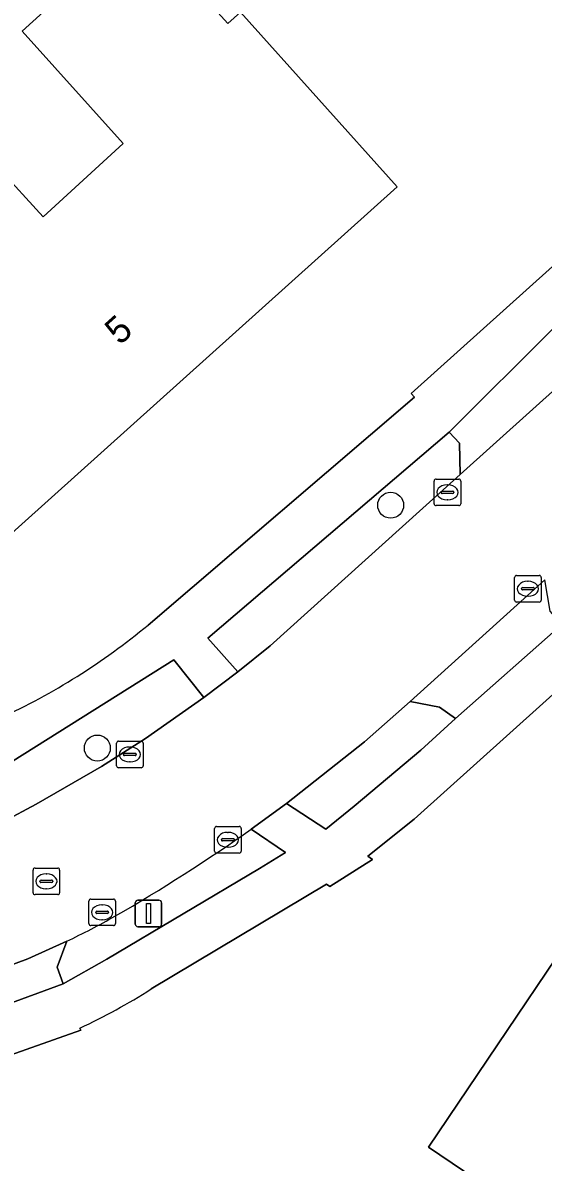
# Model space of a CAD drawing. Extents: x 163266 to 164362, y 381528 to 382286.
# Drawn here: x 163903.13 to 163922.72, y 381642.39 to 381685.27 of the extents above; entities that cross this region are included whole.
import ezdxf

# ---------------------------------------------------------------- set-up
doc = ezdxf.new("R2010")
doc.units = 0
for name, color, linetype in [('IMGEO_Boom', 7, 'Continuous'), ('IMGEO_Erf', 7, 'Continuous'), ('IMGEO_Groenvoorziening', 7, 'Continuous'), ('IMGEO_Haag', 7, 'Continuous'), ('IMGEO_Kolk', 7, 'Continuous'), ('IMGEO_Lichtmast', 7, 'Continuous'), ('IMGEO_Pand', 7, 'Continuous'), ('IMGEO_Pand_nummerreeks', 7, 'Continuous'), ('IMGEO_Rijbaan_lokaal_open', 7, 'Continuous'), ('IMGEO_Rioolput', 7, 'Continuous'), ('IMGEO_Voetpad_open', 7, 'Continuous')]:
    doc.layers.add(name, color=color, linetype=linetype)

msp = doc.modelspace()

# ---------------------------------------------------------------- linework, layer by layer
at = {"layer": 'IMGEO_Boom'}
for centre in [(163916.981, 381667.115), (163905.938, 381657.979)]:
    msp.add_circle(centre, 0.489, dxfattribs=at)
at = {"layer": 'IMGEO_Erf'}
for points in [[(163907.846, 381662.609), (163917.878, 381671.183), (163917.751, 381671.321), (163960.431, 381709.666), (163995.111, 381740.522)], [(163996.245, 381642.873), (163995.343, 381643.451), (163992.948, 381645.106), (163982.444, 381652.18), (163959.631, 381667.581), (163955.118, 381670.638), (163954.017, 381671.266), (163952.935, 381672.069), (163945.749, 381676.984), (163941.834, 381676.838), (163917.871, 381655.298), (163916.12, 381653.912), (163916.297, 381653.78), (163914.696, 381652.772), (163914.563, 381652.851), (163907.959, 381648.913)], [(163905.281, 381647.443), (163905.312, 381647.362), (163892.952, 381643.003), (163890.818, 381639.108), (163894.047, 381628.59)]]:
    msp.add_lwpolyline(points, dxfattribs=at)
for points in [[(163910.845, 381685.239), (163911.326, 381685.672), (163917.227, 381679.103), (163900.114, 381663.732), (163894.791, 381669.649), (163899.822, 381674.244), (163898.16, 381676.126), (163902.193, 381679.825), (163903.898, 381677.967), (163906.916, 381680.724), (163903.102, 381684.959), (163907.494, 381688.938)], [(163933.369, 381643.462), (163931.198, 381644.946), (163926.278, 381637.642), (163918.405, 381642.961), (163926.17, 381654.47), (163934.049, 381649.163), (163933.848, 381648.864), (163936.02, 381647.39)]]:
    msp.add_lwpolyline(points, close=True, dxfattribs=at)
for centre, radius, start, end in [((163891.772, 381681.977), 25.169, 294.6909, 309.6896), ((163895.911, 381667.688), 22.309, 294.837, 302.6892)]:
    msp.add_arc(centre, radius, start, end, dxfattribs=at)
at = {"layer": 'IMGEO_Groenvoorziening'}
for points in [[(163919.566, 381669.451), (163919.183, 381669.863), (163910.092, 381662.118), (163911.229, 381660.85), (163912.446, 381661.828), (163919.599, 381668.268)], [(163909.942, 381659.876), (163908.824, 381661.296), (163901.437, 381656.675), (163899.692, 381655.96), (163894.99, 381654.332), (163892.801, 381653.658), (163893.095, 381652.76), (163894.024, 381652.181), (163897.063, 381653.193), (163901.509, 381654.797), (163902.422, 381655.214), (163903.641, 381655.862), (163906.099, 381657.289), (163907.748, 381658.343)], [(163915.606, 381655.796), (163918.114, 381657.894), (163919.418, 381659.091), (163918.817, 381659.523), (163917.711, 381659.728), (163915.995, 381658.215), (163913.059, 381655.894), (163914.542, 381654.925)]]:
    msp.add_lwpolyline(points, close=True, dxfattribs=at)
msp.add_lwpolyline([(163904.788, 381650.707), (163904.431, 381649.731), (163904.646, 381649.112), (163906.295, 381650.033), (163912.044, 381653.452), (163913.023, 381654.044), (163911.734, 381654.932)], dxfattribs=at)
for centre, radius, start, end in [((163873.791, 381708.646), 65.764, 299.92642, 305.23666), ((163889.367, 381682.518), 35.352, 295.8623, 299.1741)]:
    msp.add_arc(centre, radius, start, end, dxfattribs=at)
at = {"layer": 'IMGEO_Haag'}
for points in [[(163919.599, 381668.268), (163919.566, 381669.451), (163919.183, 381669.863), (163910.092, 381662.118), (163911.229, 381660.85), (163912.446, 381661.828)], [(163894.024, 381652.181), (163897.063, 381653.193), (163901.509, 381654.797), (163902.422, 381655.214), (163903.641, 381655.862), (163906.099, 381657.289), (163907.748, 381658.343), (163909.942, 381659.876), (163908.824, 381661.296), (163901.437, 381656.675), (163899.692, 381655.96), (163894.99, 381654.332), (163892.801, 381653.658), (163893.095, 381652.76)], [(163918.114, 381657.894), (163919.418, 381659.091), (163918.817, 381659.523), (163917.711, 381659.728), (163915.995, 381658.215), (163913.059, 381655.894), (163914.542, 381654.925), (163915.606, 381655.796)]]:
    msp.add_lwpolyline(points, close=True, dxfattribs=at)
msp.add_lwpolyline([(163904.788, 381650.707), (163904.431, 381649.731), (163904.646, 381649.112), (163906.295, 381650.033), (163912.044, 381653.452), (163913.023, 381654.044), (163911.734, 381654.932)], dxfattribs=at)
for centre, radius, start, end in [((163873.791, 381708.646), 65.764, 299.92642, 305.23666), ((163889.367, 381682.518), 35.352, 295.8623, 299.1741)]:
    msp.add_arc(centre, radius, start, end, dxfattribs=at)
at = {"layer": 'IMGEO_Kolk'}
for p, q in [((163918.617, 381667.175), (163918.617, 381668.027)), ((163918.692, 381668.101), (163919.544, 381668.101)), ((163919.618, 381668.027), (163919.618, 381667.175)), ((163918.876, 381667.595), (163918.876, 381667.607)), ((163919.314, 381667.558), (163918.916, 381667.558)), ((163918.919, 381667.644), (163919.317, 381667.644)), ((163919.105, 381667.881), (163919.13, 381667.881)), ((163919.36, 381667.607), (163919.36, 381667.595)), ((163919.544, 381667.101), (163918.692, 381667.101)), ((163919.128, 381667.321), (163919.103, 381667.321)), ((163921.723, 381664.473), (163922.575, 381664.473)), ((163921.648, 381663.547), (163921.648, 381664.399)), ((163922.136, 381664.253), (163922.161, 381664.253)), ((163922.649, 381664.399), (163922.649, 381663.547)), ((163921.907, 381663.967), (163921.907, 381663.979)), ((163922.345, 381663.93), (163921.947, 381663.93)), ((163921.95, 381664.016), (163922.348, 381664.016)), ((163922.159, 381663.693), (163922.134, 381663.693)), ((163922.391, 381663.979), (163922.391, 381663.967)), ((163922.575, 381663.473), (163921.723, 381663.473)), ((163906.663, 381657.312), (163906.663, 381658.164)), ((163906.738, 381658.238), (163907.59, 381658.238)), ((163907.664, 381658.164), (163907.664, 381657.312)), ((163906.922, 381657.732), (163906.922, 381657.744)), ((163907.36, 381657.695), (163906.962, 381657.695)), ((163906.965, 381657.781), (163907.363, 381657.781)), ((163907.151, 381658.018), (163907.176, 381658.018)), ((163907.406, 381657.744), (163907.406, 381657.732)), ((163907.59, 381657.238), (163906.738, 381657.238)), ((163907.174, 381657.458), (163907.149, 381657.458)), ((163910.354, 381654.101), (163910.354, 381654.953)), ((163910.429, 381655.027), (163911.281, 381655.027)), ((163910.842, 381654.807), (163910.867, 381654.807)), ((163911.355, 381654.953), (163911.355, 381654.101)), ((163910.613, 381654.521), (163910.613, 381654.533)), ((163911.051, 381654.484), (163910.653, 381654.484)), ((163910.656, 381654.57), (163911.054, 381654.57)), ((163910.865, 381654.247), (163910.84, 381654.247)), ((163911.097, 381654.533), (163911.097, 381654.521)), ((163911.281, 381654.027), (163910.429, 381654.027))]:
    msp.add_line(p, q, dxfattribs=at)
for points in [[(163918.617, 381667.175), (163918.617, 381668.027)], [(163918.692, 381668.101), (163919.544, 381668.101)], [(163919.618, 381668.027), (163919.618, 381667.175)], [(163919.544, 381667.101), (163918.692, 381667.101)], [(163921.723, 381664.473), (163922.575, 381664.473)], [(163921.648, 381663.547), (163921.648, 381664.399)], [(163922.649, 381664.399), (163922.649, 381663.547)], [(163922.575, 381663.473), (163921.723, 381663.473)], [(163906.663, 381657.312), (163906.663, 381658.164)], [(163906.738, 381658.238), (163907.59, 381658.238)], [(163907.664, 381658.164), (163907.664, 381657.312)], [(163907.59, 381657.238), (163906.738, 381657.238)], [(163910.354, 381654.101), (163910.354, 381654.953)], [(163910.429, 381655.027), (163911.281, 381655.027)], [(163911.355, 381654.953), (163911.355, 381654.101)], [(163911.281, 381654.027), (163910.429, 381654.027)]]:
    msp.add_lwpolyline(points, dxfattribs=at)
for centre, radius, start, end in [((163918.694, 381668.025), 0.0765, 91.552, 178.448), ((163918.694, 381668.025), 0.0765, 91.552, 178.448), ((163919.542, 381668.025), 0.0765, 1.552, 88.448), ((163919.542, 381668.025), 0.0765, 1.552, 88.448), ((163918.916, 381667.604), 0.0403, 85.8775, 175.7526), ((163918.913, 381667.594), 0.0366, 178.938, 274.7102), ((163919.317, 381667.601), 0.043, 264.8664, 352.4533), ((163919.321, 381667.606), 0.0386, 1.7309, 96.639), ((163918.694, 381667.177), 0.0765, 181.552, 268.448), ((163918.694, 381667.177), 0.0765, 181.552, 268.448), ((163919.542, 381667.177), 0.0765, 271.552, 358.448), ((163919.542, 381667.177), 0.0765, 271.552, 358.448), ((163921.725, 381664.397), 0.0765, 91.552, 178.448), ((163921.725, 381664.397), 0.0765, 91.552, 178.448), ((163922.573, 381664.397), 0.0765, 1.552, 88.448), ((163922.573, 381664.397), 0.0765, 1.552, 88.448), ((163921.947, 381663.976), 0.0403, 85.8775, 175.7526), ((163921.944, 381663.966), 0.0366, 178.938, 274.7102), ((163922.348, 381663.973), 0.043, 264.8664, 352.4533), ((163922.352, 381663.978), 0.0386, 1.7309, 96.639), ((163921.725, 381663.549), 0.0765, 181.552, 268.448), ((163921.725, 381663.549), 0.0765, 181.552, 268.448), ((163922.573, 381663.549), 0.0765, 271.552, 358.448), ((163922.573, 381663.549), 0.0765, 271.552, 358.448), ((163906.74, 381658.162), 0.0765, 91.552, 178.448), ((163906.74, 381658.162), 0.0765, 91.552, 178.448), ((163907.588, 381658.162), 0.0765, 1.552, 88.448), ((163907.588, 381658.162), 0.0765, 1.552, 88.448), ((163906.962, 381657.741), 0.0403, 85.8775, 175.7526), ((163906.959, 381657.731), 0.0366, 178.938, 274.7102), ((163907.363, 381657.738), 0.043, 264.8664, 352.4533), ((163907.367, 381657.743), 0.0386, 1.7309, 96.639), ((163906.74, 381657.314), 0.0765, 181.552, 268.448), ((163906.74, 381657.314), 0.0765, 181.552, 268.448), ((163907.588, 381657.314), 0.0765, 271.552, 358.448), ((163907.588, 381657.314), 0.0765, 271.552, 358.448), ((163910.431, 381654.951), 0.0765, 91.552, 178.448), ((163910.431, 381654.951), 0.0765, 91.552, 178.448), ((163911.279, 381654.951), 0.0765, 1.552, 88.448), ((163911.279, 381654.951), 0.0765, 1.552, 88.448), ((163910.653, 381654.53), 0.0403, 85.8775, 175.7526), ((163910.65, 381654.52), 0.0366, 178.938, 274.7102), ((163911.054, 381654.527), 0.043, 264.8664, 352.4533), ((163911.058, 381654.532), 0.0386, 1.7309, 96.639), ((163910.431, 381654.103), 0.0765, 181.552, 268.448), ((163910.431, 381654.103), 0.0765, 181.552, 268.448), ((163911.279, 381654.103), 0.0765, 271.552, 358.448), ((163911.279, 381654.103), 0.0765, 271.552, 358.448)]:
    msp.add_arc(centre, radius, start, end, dxfattribs=at)
for centre, major_axis, ratio, start_param, end_param in [((163919.104, 381667.601), (-0.387, 0.002), 0.722429, 4.712389, 7.853982), ((163919.129, 381667.601), (-0.39, 0.002), 0.717154, 1.570796, 4.712389), ((163922.135, 381663.973), (-0.387, 0.002), 0.722429, 4.712389, 7.853982), ((163922.16, 381663.973), (-0.39, 0.002), 0.717154, 1.570796, 4.712389), ((163907.15, 381657.738), (-0.387, 0.002), 0.722429, 4.712389, 7.853982), ((163907.175, 381657.738), (-0.39, 0.002), 0.717154, 1.570796, 4.712389), ((163910.841, 381654.527), (-0.387, 0.002), 0.722429, 4.712389, 7.853982), ((163910.866, 381654.527), (-0.39, 0.002), 0.717154, 1.570796, 4.712389)]:
    msp.add_ellipse(centre, major_axis=major_axis, ratio=ratio, start_param=start_param, end_param=end_param, dxfattribs=at)
at = {"layer": 'IMGEO_Lichtmast'}
for p, q in [((163907.368, 381651.354), (163907.368, 381652.154)), ((163907.368, 381652.154), (163907.368, 381651.354)), ((163907.468, 381652.254), (163908.258, 381652.254)), ((163908.258, 381652.254), (163907.468, 381652.254)), ((163908.358, 381652.154), (163908.358, 381651.354)), ((163908.358, 381651.354), (163908.358, 381652.154)), ((163908.258, 381651.254), (163907.468, 381651.254)), ((163907.468, 381651.254), (163908.258, 381651.254))]:
    msp.add_line(p, q, dxfattribs=at)
msp.add_lwpolyline([(163907.788, 381652.129), (163907.938, 381652.129), (163907.938, 381651.379), (163907.788, 381651.379), (163907.788, 381652.129)], dxfattribs=at)
for centre, start, end in [((163907.468, 381652.154), 90, 180), ((163907.468, 381652.154), 90, 180), ((163908.258, 381652.154), 0, 90), ((163908.258, 381652.154), 360, 90), ((163907.468, 381651.354), 180, 270), ((163907.468, 381651.354), 180, 270), ((163908.258, 381651.354), 270, 0), ((163908.258, 381651.354), 270, 0)]:
    msp.add_arc(centre, 0.1, start, end, dxfattribs=at)
at = {"layer": 'IMGEO_Pand'}
for points in [[(163900.114, 381663.732), (163917.227, 381679.103), (163911.326, 381685.672), (163910.845, 381685.239), (163907.494, 381688.938), (163903.102, 381684.959), (163906.916, 381680.724), (163903.898, 381677.967), (163902.193, 381679.825), (163898.16, 381676.126), (163899.822, 381674.244), (163894.791, 381669.649)], [(163931.198, 381644.946), (163933.369, 381643.462), (163936.02, 381647.39), (163933.848, 381648.864), (163934.049, 381649.163), (163926.17, 381654.47), (163918.405, 381642.961), (163926.278, 381637.642)]]:
    msp.add_lwpolyline(points, close=True, dxfattribs=at)
at = {"layer": 'IMGEO_Rijbaan_lokaal_open'}
for points in [[(163924.816, 381672.964), (163919.599, 381668.268), (163912.446, 381661.828), (163911.229, 381660.85), (163909.942, 381659.876), (163907.748, 381658.343), (163906.099, 381657.289), (163903.641, 381655.862), (163902.422, 381655.214), (163901.509, 381654.797), (163897.063, 381653.193), (163894.024, 381652.181), (163887.447, 381650.131), (163874.425, 381646.069)], [(163911.734, 381654.932), (163913.059, 381655.894), (163915.995, 381658.215), (163917.711, 381659.728), (163922.79, 381664.306)], [(163892.869, 381646.488), (163899.123, 381648.496), (163903.327, 381650.044), (163904.788, 381650.707)]]:
    msp.add_lwpolyline(points, dxfattribs=at)
for centre, radius, start, end in [((163873.791, 381708.646), 65.764, 299.92642, 305.23666), ((163889.367, 381682.518), 35.352, 295.8623, 299.1741)]:
    msp.add_arc(centre, radius, start, end, dxfattribs=at)
at = {"layer": 'IMGEO_Rioolput'}
for p, q in [((163903.518, 381652.537), (163903.518, 381653.389)), ((163903.593, 381653.463), (163904.445, 381653.463)), ((163904.519, 381653.389), (163904.519, 381652.537)), ((163903.777, 381652.957), (163903.777, 381652.969)), ((163904.215, 381652.92), (163903.817, 381652.92)), ((163903.82, 381653.006), (163904.218, 381653.006)), ((163904.006, 381653.243), (163904.031, 381653.243)), ((163904.261, 381652.969), (163904.261, 381652.957)), ((163904.445, 381652.463), (163903.593, 381652.463)), ((163904.029, 381652.683), (163904.004, 381652.683)), ((163905.619, 381651.371), (163905.619, 381652.223)), ((163905.694, 381652.297), (163906.546, 381652.297)), ((163906.107, 381652.077), (163906.132, 381652.077)), ((163906.62, 381652.223), (163906.62, 381651.371)), ((163905.878, 381651.791), (163905.878, 381651.803)), ((163906.316, 381651.754), (163905.918, 381651.754)), ((163905.921, 381651.84), (163906.319, 381651.84)), ((163906.362, 381651.803), (163906.362, 381651.791)), ((163906.546, 381651.297), (163905.694, 381651.297)), ((163906.13, 381651.517), (163906.105, 381651.517))]:
    msp.add_line(p, q, dxfattribs=at)
for points in [[(163903.518, 381652.537), (163903.518, 381653.389)], [(163903.593, 381653.463), (163904.445, 381653.463)], [(163904.519, 381653.389), (163904.519, 381652.537)], [(163904.445, 381652.463), (163903.593, 381652.463)], [(163905.619, 381651.371), (163905.619, 381652.223)], [(163905.694, 381652.297), (163906.546, 381652.297)], [(163906.62, 381652.223), (163906.62, 381651.371)], [(163906.546, 381651.297), (163905.694, 381651.297)]]:
    msp.add_lwpolyline(points, dxfattribs=at)
for centre, radius, start, end in [((163903.595, 381653.387), 0.0765, 91.552, 178.448), ((163903.595, 381653.387), 0.0765, 91.552, 178.448), ((163904.443, 381653.387), 0.0765, 1.552, 88.448), ((163904.443, 381653.387), 0.0765, 1.552, 88.448), ((163903.817, 381652.966), 0.0403, 85.8775, 175.7526), ((163903.814, 381652.956), 0.0366, 178.938, 274.7102), ((163904.218, 381652.963), 0.043, 264.8664, 352.4533), ((163904.222, 381652.968), 0.0386, 1.7309, 96.639), ((163903.595, 381652.539), 0.0765, 181.552, 268.448), ((163903.595, 381652.539), 0.0765, 181.552, 268.448), ((163904.443, 381652.539), 0.0765, 271.552, 358.448), ((163904.443, 381652.539), 0.0765, 271.552, 358.448), ((163905.696, 381652.221), 0.0765, 91.552, 178.448), ((163905.696, 381652.221), 0.0765, 91.552, 178.448), ((163906.544, 381652.221), 0.0765, 1.552, 88.448), ((163906.544, 381652.221), 0.0765, 1.552, 88.448), ((163905.918, 381651.8), 0.0403, 85.8775, 175.7526), ((163905.915, 381651.79), 0.0366, 178.938, 274.7102), ((163906.319, 381651.797), 0.043, 264.8664, 352.4533), ((163906.323, 381651.802), 0.0386, 1.7309, 96.639), ((163905.696, 381651.373), 0.0765, 181.552, 268.448), ((163905.696, 381651.373), 0.0765, 181.552, 268.448), ((163906.544, 381651.373), 0.0765, 271.552, 358.448), ((163906.544, 381651.373), 0.0765, 271.552, 358.448)]:
    msp.add_arc(centre, radius, start, end, dxfattribs=at)
for centre, major_axis, ratio, start_param, end_param in [((163904.005, 381652.963), (-0.387, 0.002), 0.722429, 4.712389, 7.853982), ((163904.03, 381652.963), (-0.39, 0.002), 0.717154, 1.570796, 4.712389), ((163906.106, 381651.797), (-0.387, 0.002), 0.722429, 4.712389, 7.853982), ((163906.131, 381651.797), (-0.39, 0.002), 0.717154, 1.570796, 4.712389)]:
    msp.add_ellipse(centre, major_axis=major_axis, ratio=ratio, start_param=start_param, end_param=end_param, dxfattribs=at)
at = {"layer": 'IMGEO_Voetpad_open'}
for points in [[(163995.111, 381740.522), (163960.431, 381709.666), (163917.751, 381671.321), (163917.878, 381671.183), (163907.846, 381662.609)], [(163902.286, 381659.109), (163900.588, 381658.268), (163901.437, 381656.675), (163908.824, 381661.296), (163909.942, 381659.876), (163911.229, 381660.85), (163910.092, 381662.118), (163919.183, 381669.863), (163923.136, 381673.808), (163938.9, 381687.899)], [(163942.762, 381680.116), (163923.941, 381663.122), (163923.429, 381662.631), (163919.418, 381659.091), (163918.114, 381657.894), (163915.606, 381655.796), (163914.542, 381654.925), (163913.059, 381655.894), (163911.734, 381654.932), (163913.023, 381654.044), (163912.044, 381653.452), (163906.295, 381650.033), (163904.646, 381649.112), (163900.305, 381647.52), (163889.487, 381643.701)], [(163907.959, 381648.913), (163914.563, 381652.851), (163914.696, 381652.772), (163916.297, 381653.78), (163916.12, 381653.912), (163917.871, 381655.298), (163941.834, 381676.838), (163945.749, 381676.984), (163946.802, 381678.493), (163945.742, 381679.21)], [(163889.087, 381638.571), (163890.818, 381639.108), (163892.952, 381643.003), (163905.312, 381647.362), (163905.281, 381647.443)]]:
    msp.add_lwpolyline(points, dxfattribs=at)
for points in [[(163919.599, 381668.268), (163924.816, 381672.964), (163923.696, 381673.208), (163923.136, 381673.808), (163919.183, 381669.863), (163919.566, 381669.451)], [(163922.79, 381664.306), (163917.711, 381659.728), (163918.817, 381659.523), (163919.418, 381659.091), (163923.429, 381662.631), (163922.988, 381663.132)], [(163900.305, 381647.52), (163904.646, 381649.112), (163904.431, 381649.731), (163904.788, 381650.707), (163903.327, 381650.044), (163899.123, 381648.496), (163900.015, 381648.091)]]:
    msp.add_lwpolyline(points, close=True, dxfattribs=at)
for centre, radius, start, end in [((163891.772, 381681.977), 25.169, 294.6909, 309.6896), ((163895.911, 381667.688), 22.309, 294.837, 302.6892)]:
    msp.add_arc(centre, radius, start, end, dxfattribs=at)

# ---------------------------------------------------------------- texts
at = {"layer": 'IMGEO_Pand_nummerreeks'}
msp.add_text('5', height=1, rotation=41.9302, dxfattribs=at).set_placement((163906.784, 381673.111))

doc.saveas('drawing.dxf')
